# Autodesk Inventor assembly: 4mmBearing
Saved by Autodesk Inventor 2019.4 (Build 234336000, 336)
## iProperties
Created: 2020-02
Part Number: 4mmBearing
Document SubType Name: Assembly
Designer: Administrator
Title: 4mmBearing v4
Author: Administrator
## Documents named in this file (2)
- c:\worker\convert-fusion-r01\tmp\job-1\5\output\files\e4333473-a38b-4431-9958-ad24a2f67704\4mmBearing v4.iam
- c:\worker\convert-fusion-r01\tmp\job-1\5\output\files\e4333473-a38b-4431-9958-ad24a2f67704\4mmBearing.ipt
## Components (1 placed, 1 different names)
1. 4mmBearing:1
